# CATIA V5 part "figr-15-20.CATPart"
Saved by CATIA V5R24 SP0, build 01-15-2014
Part number: Part1
Bounding box of the stored display mesh (mm): x -81.56 to 85.56, y -36.965 to 25.965, z 0 to 42
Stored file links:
  D:\KAVITA\CATIA V5-6R2014 Project_ Kavita\CATIA V5-6R2014_partfiles\Partfiles\c15_catia_v5-6r2014_prt\figr-15-20.CATPart
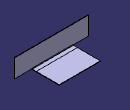
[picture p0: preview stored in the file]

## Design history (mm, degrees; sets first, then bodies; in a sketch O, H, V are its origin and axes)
SheetMetalParameters1: Thickness 1, BendRadius 1, KFactor 0.325257 {= log(min(100,max(20*SheetMetalParameters1.BendRadius,SheetMetalParameters1.Thickness)/SheetMetalParameters1.Thickness))/log(100)/2}, ReliefRadialLength 1, ReliefAxialLength 2, MinimumBendRadius 0
Body1 (main body)
  Sketch1 on xy-plane, origin (0, 0, 0), H (1, 0, 0), V (0, 1, 0)
    line L1 (-46.5596, 25.9646) -> (46.5596, 25.9646)
    line L2 (46.5596, 25.9646) -> (46.5596, -25.9646)
    line L3 (46.5596, -25.9646) -> (-46.5596, -25.9646)
    line L4 (-46.5596, -25.9646) -> (-46.5596, 25.9646)
    horizontal: L1 H, L3 H
    vertical: L2 V, L4 V
    symmetry: L1 L3 H, L4 L2 V
  Wall1: Thickness 1, Profile Sketch1
  d_NewWallOnEdge1: NewWallOnEdge_Edge edge [face of Wall1 | face of Wall1], NewWallOnEdge_Length 42, NewWallOnEdge_HeightLimitOffset 0, NewWallOnEdge_WidthOffset1 39, NewWallOnEdge_WidthOffset2 35, NewWallOnEdge_Angle 90, NewWallOnEdge_BendRadiusValue 1 {= SheetMetalParameters1.BendRadius}, NewWallOnEdge_BendTable SheetMetalParameters1, KFacteur 0.325257 {= log(min(100,max(20*d_NewWallOnEdge1.Radius,SheetMetalParameters1.Thickness)/SheetMetalParameters1.Thickness))/log(100)/2}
